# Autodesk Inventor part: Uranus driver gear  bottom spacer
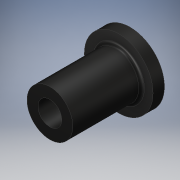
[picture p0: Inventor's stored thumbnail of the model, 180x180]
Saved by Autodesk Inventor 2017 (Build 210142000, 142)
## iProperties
Created: 2016-07
Part Number: Uranus driver gear  bottom spacer
Material: Generic
Document SubType Name: Modeling
Designer: Stan
Density: 1 g/cm^3
Appearance: Glossy - Black
Author: Stan
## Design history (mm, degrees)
sketch "Sketch1"
  geometry: C1 r 9.525 at (0, 0); 1 further point
  constraints: 1 centre point, 1 coincident
  dimensions: "d0" = 19.05 diameter of C1
extrude "Extrusion1" new body sketch "Sketch1" distance "d1" = 3.175; taper "d2" = 0 deg
sketch "Sketch2"
  geometry: C1 r 6.35 at (0, 0); 1 further point
  constraints: 1 centre point, 1 coincident
  dimensions: "d3" = 12.7 diameter of C1
extrude "Extrusion2" join sketch "Sketch2" distance "d4" = 19.05; taper "d5" = 0 deg
sketch "Sketch3"
  geometry: C1 r 3.302 at (0, 0); 1 further point
  constraints: 1 centre point, 1 coincident
  dimensions: "d6" = 6.604 diameter of C1
extrude "Extrusion3" cut sketch "Sketch3" distance "d7" = 22.225; taper "d8" = 0 deg
fillet "Fillet1" dims "d9" = 0.79375
fillet "Fillet2" dims "d10" = 0.79375
body "Solid1"
